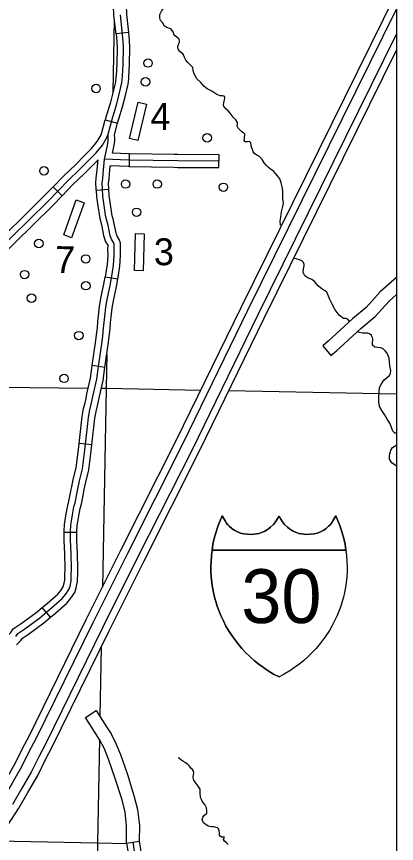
# Model space of a CAD drawing. Extents: x 1369979 to 1371646, y 379997 to 381064.
# Drawn here: x 1371088 to 1371140.4, y 380415 to 380529.1 of the extents above; entities that cross this region are included whole.
import ezdxf

# ---------------------------------------------------------------- set-up
doc = ezdxf.new("R2010")
doc.units = 0
doc.layers.add('R_Border Notes', color=7, linetype='Continuous')
doc.layers.add('R_No Plot', color=7, linetype='Continuous')

msp = doc.modelspace()

# ---------------------------------------------------------------- linework, layer by layer
at = {"layer": 'R_Border Notes'}
for p, q in [((1371103.48, 380526.85), (1371101.74, 380526.66)), ((1371140.38, 380526.67), (1371121.22, 380487.83)), ((1371122.11, 380487.39), (1371140.38, 380524.42)), ((1371101.73, 380520.69), (1371101.73, 380520.69)), ((1371100.26, 380514.82), (1371101.96, 380514.35)), ((1371103.56, 380510.15), (1371103.53, 380508.39)), ((1371109.75, 380510.04), (1371109.75, 380510.04)), ((1371115.92, 380508.25), (1371115.93, 380510)), ((1371094.33, 380504.36), (1371093.07, 380505.59)), ((1371093.07, 380505.59), (1371093.07, 380505.59)), ((1371100.74, 380505.22), (1371098.99, 380505.08)), ((1371098.99, 380505.08), (1371098.99, 380505.08)), ((1371100.24, 380493.19), (1371101.97, 380492.88)), ((1371121.22, 380487.83), (1371112.21, 380469.29)), ((1371113.26, 380469.17), (1371122.11, 380487.39)), ((1371130.22, 380483.65), (1371131.34, 380482.3)), ((1371100.21, 380480.67), (1371098.47, 380480.92)), ((1371098.42, 380470.01), (1371096.67, 380470.2)), ((1371112.21, 380469.29), (1371104.66, 380454.35)), ((1371105.55, 380453.9), (1371113.26, 380469.17)), ((1371096.34, 380457.93), (1371094.58, 380457.93)), ((1371133.43, 380455.45), (1371133.41, 380455.45)), ((1371104.66, 380454.35), (1371099.88, 380444.78)), ((1371100.77, 380444.33), (1371105.55, 380453.9)), ((1371092.71, 380446.24), (1371091.56, 380447.57)), ((1371099.88, 380444.78), (1371092.01, 380428.71)), ((1371092.91, 380428.27), (1371100.77, 380444.33)), ((1371103.19, 380415.08), (1371104.92, 380415.35))]:
    msp.add_line(p, q, dxfattribs=at)
for points in [[(1371109.63, 380526.97), (1371109.3, 380527.37), (1371108.98, 380527.48), (1371108.63, 380527.58), (1371108.39, 380527.8), (1371108.17, 380528.18), (1371107.86, 380528.53), (1371107.77, 380528.87), (1371107.77, 380529.35), (1371107.99, 380529.83), (1371108.41, 380530.38), (1371108.53, 380530.66), (1371108.87, 380531.26), (1371108.93, 380531.52), (1371109.11, 380531.92), (1371109.11, 380532.33), (1371108.9, 380532.81), (1371108.79, 380533.06), (1371108.6, 380533.56), (1371108.52, 380533.99), (1371108.53, 380534.45), (1371108.69, 380535.02), (1371108.88, 380535.57)], [(1371101.74, 380526.66), (1371101.45, 380529.23), (1371101.36, 380532.01), (1371101.4, 380532.79), (1371101.51, 380533.16)], [(1371103.48, 380526.85), (1371103.21, 380529.36), (1371103.12, 380531.99), (1371103.15, 380532.5), (1371103.2, 380532.67)], [(1371118.96, 380488.96), (1371140.38, 380532.36)], [(1371084.95, 380496.13), (1371085.29, 380496.48), (1371085.84, 380497.09), (1371086.77, 380498.08), (1371087.55, 380498.85), (1371089.73, 380501), (1371092.34, 380503.57), (1371095.18, 380506.51), (1371096.7, 380507.96), (1371099, 380510.28), (1371099.86, 380511.34), (1371100.49, 380512.37), (1371100.63, 380512.85), (1371101.29, 380515.23), (1371101.8, 380516.85), (1371102.12, 380518.18), (1371102.52, 380519.91), (1371102.63, 380520.84), (1371102.71, 380522.52), (1371102.77, 380524.78), (1371102.73, 380525.68), (1371102.33, 380529.3)], [(1371140.38, 380530.11), (1371119.86, 380488.51)], [(1371101.49, 380528.67), (1371101.28, 380518.65)], [(1371103.48, 380520.48), (1371103.51, 380520.77), (1371103.59, 380522.49), (1371103.65, 380524.79), (1371103.61, 380525.75), (1371103.48, 380526.85)], [(1371112.88, 380520.47), (1371112.47, 380521.26), (1371112.39, 380521.67), (1371112.33, 380522.02), (1371112.02, 380522.36), (1371111.61, 380522.74), (1371111.34, 380523.04), (1371111.15, 380523.44), (1371111.05, 380523.78), (1371110.96, 380523.92), (1371110.78, 380524.05), (1371110.57, 380524.22), (1371110.33, 380524.49), (1371110.24, 380524.73), (1371110.24, 380524.97), (1371110.35, 380525.2), (1371110.49, 380525.48), (1371110.48, 380525.69), (1371110.43, 380525.93), (1371110.13, 380526.2), (1371109.92, 380526.36), (1371109.74, 380526.52), (1371109.63, 380526.97)], [(1371101.74, 380526.66), (1371101.85, 380525.62), (1371101.89, 380524.77), (1371101.83, 380522.55), (1371101.76, 380520.92), (1371101.73, 380520.69)], [(1371101.73, 380520.69), (1371101.65, 380520.06), (1371101.27, 380518.38), (1371100.95, 380517.08), (1371100.44, 380515.48), (1371100.26, 380514.82)], [(1371101.96, 380514.35), (1371102.13, 380514.98), (1371102.65, 380516.61), (1371102.98, 380517.98), (1371103.39, 380519.76), (1371103.48, 380520.48)], [(1371118.44, 380513.93), (1371118.5, 380514.28), (1371118.46, 380514.47), (1371118.26, 380514.81), (1371117.88, 380515.19), (1371117.45, 380515.75), (1371117.17, 380516.05), (1371116.86, 380516.35), (1371116.59, 380516.69), (1371116.56, 380516.91), (1371116.58, 380517.18), (1371116.7, 380517.6), (1371116.74, 380517.77), (1371116.74, 380517.95), (1371116.64, 380518.07), (1371116.43, 380518.12), (1371116.11, 380518.12), (1371115.65, 380518.33), (1371114.92, 380518.78), (1371114.3, 380519.08), (1371113.85, 380519.46), (1371113.41, 380519.96), (1371112.88, 380520.47)], [(1371097.45, 380509.96), (1371098.35, 380510.86), (1371099.14, 380511.85), (1371099.68, 380512.73), (1371099.79, 380513.09), (1371100.26, 380514.82)], [(1371101.52, 380512.76), (1371101.96, 380514.35)], [(1371124.48, 380506.13), (1371124.32, 380506.67), (1371124.03, 380507.05), (1371123.76, 380507.36), (1371123.43, 380507.72), (1371123.01, 380508.03), (1371122.71, 380508.3), (1371122.49, 380508.52), (1371122.14, 380508.9), (1371121.88, 380509.33), (1371121.53, 380509.75), (1371121.13, 380509.96), (1371120.83, 380510.18), (1371120.65, 380510.4), (1371120.54, 380510.74), (1371120.42, 380511.07), (1371120.35, 380511.37), (1371120.3, 380511.63), (1371120.19, 380511.76), (1371120.08, 380511.82), (1371119.84, 380511.77), (1371119.54, 380511.77), (1371119.41, 380511.96), (1371119.46, 380512.2), (1371119.43, 380512.41), (1371119.49, 380512.67), (1371119.48, 380512.84), (1371119.3, 380513.02), (1371119.08, 380513.18), (1371118.84, 380513.38), (1371118.55, 380513.65), (1371118.44, 380513.93)], [(1371101.47, 380496.09), (1371101.46, 380496.98), (1371101.49, 380497.67), (1371101.38, 380497.92), (1371101.1, 380498.38), (1371100.94, 380498.83), (1371100.65, 380500.3), (1371100.47, 380500.94), (1371100.35, 380501.4), (1371100.06, 380503.34), (1371099.94, 380504.29), (1371099.86, 380505.3), (1371099.83, 380506.08), (1371099.9, 380506.75), (1371099.95, 380507.4), (1371100.16, 380509.41), (1371100.58, 380511.28), (1371100.67, 380511.95), (1371100.67, 380512.26), (1371100.63, 380512.85)], [(1371101.44, 380511.12), (1371101.55, 380511.89), (1371101.55, 380512.29), (1371101.52, 380512.76)], [(1371101.25, 380510.24), (1371101.44, 380511.09)], [(1371093.07, 380505.59), (1371094.57, 380507.14), (1371096.09, 380508.59), (1371097.45, 380509.96)], [(1371103.56, 380510.15), (1371103.47, 380510.15), (1371101.25, 380510.24)], [(1371109.75, 380510.04), (1371103.56, 380510.15)], [(1371115.93, 380510), (1371110.27, 380510.03), (1371109.75, 380510.04)], [(1371094.33, 380504.36), (1371095.8, 380505.89), (1371097.32, 380507.33), (1371099.27, 380509.3)], [(1371098.99, 380505.08), (1371098.98, 380505.25), (1371098.95, 380506.11), (1371099.02, 380506.83), (1371099.08, 380507.49), (1371099.27, 380509.3)], [(1371115.92, 380509.12), (1371110.26, 380509.15), (1371103.44, 380509.27), (1371100.16, 380509.41)], [(1371100.74, 380505.22), (1371100.74, 380505.35), (1371100.71, 380506.06), (1371100.77, 380506.67), (1371100.83, 380507.32), (1371100.95, 380508.5)], [(1371103.53, 380508.39), (1371103.42, 380508.39), (1371100.95, 380508.5)], [(1371103.53, 380508.39), (1371109.72, 380508.28)], [(1371109.72, 380508.28), (1371110.25, 380508.27), (1371115.92, 380508.25)], [(1371093.07, 380505.59), (1371091.71, 380504.19), (1371089.12, 380501.63), (1371088.71, 380501.23)], [(1371098.99, 380505.08), (1371099.06, 380504.2), (1371099.19, 380503.22), (1371099.49, 380501.23), (1371099.62, 380500.71), (1371099.79, 380500.1), (1371100.03, 380498.89)], [(1371101.76, 380499.23), (1371101.5, 380500.5), (1371101.32, 380501.16), (1371101.21, 380501.58), (1371100.93, 380503.46), (1371100.81, 380504.38), (1371100.74, 380505.22)], [(1371124.41, 380500.29), (1371124.37, 380500.85), (1371124.46, 380501.4), (1371124.53, 380502.15), (1371124.72, 380502.85), (1371124.8, 380503.32), (1371124.73, 380503.94), (1371124.73, 380504.88), (1371124.67, 380505.39)], [(1371124.67, 380505.39), (1371124.48, 380506.13)], [(1371089.94, 380499.97), (1371090.35, 380500.38), (1371092.96, 380502.95), (1371094.33, 380504.36)], [(1371088.71, 380501.23), (1371086.93, 380499.48), (1371086.14, 380498.7), (1371085.19, 380497.69), (1371084.64, 380497.08), (1371084.36, 380496.77)], [(1371085.64, 380495.58), (1371085.93, 380495.89), (1371086.48, 380496.5), (1371087.4, 380497.47), (1371088.17, 380498.23), (1371089.94, 380499.97)], [(1371124.46, 380499.74), (1371124.46, 380499.75)], [(1371100.03, 380498.89), (1371100.09, 380498.6), (1371100.3, 380497.99), (1371100.6, 380497.52), (1371100.6, 380497.51), (1371100.58, 380496.99), (1371100.59, 380496.11), (1371100.51, 380494.86), (1371100.33, 380493.7), (1371100.24, 380493.19)], [(1371101.97, 380492.88), (1371102.06, 380493.41), (1371102.25, 380494.66), (1371102.35, 380496.06), (1371102.34, 380496.97), (1371102.37, 380497.83), (1371102.16, 380498.32), (1371101.9, 380498.76), (1371101.79, 380499.06), (1371101.76, 380499.23)], [(1371100.91, 380491.99), (1371101.19, 380493.55), (1371101.38, 380494.76), (1371101.47, 380496.09)], [(1371133.07, 380487.44), (1371132.5, 380487.86), (1371131.94, 380488.64), (1371131.51, 380489.41), (1371131.18, 380490.03), (1371130.92, 380490.73), (1371130.78, 380491.04), (1371130.54, 380491.24), (1371130.16, 380491.47), (1371129.62, 380491.9), (1371129.33, 380492.26), (1371129.08, 380492.54), (1371128.74, 380492.82), (1371128.15, 380493.03), (1371127.77, 380493.3), (1371127.52, 380493.78), (1371127.56, 380494.27), (1371127.67, 380494.7), (1371127.66, 380494.88), (1371127.58, 380495.13), (1371127.34, 380495.37), (1371127.01, 380495.53), (1371126.7, 380495.6), (1371126.23, 380495.74)], [(1371099.23, 380487.01), (1371099.3, 380487.8), (1371099.48, 380489.11), (1371099.65, 380490.18), (1371099.82, 380491.09), (1371100.05, 380492.16), (1371100.24, 380493.19)], [(1371100.98, 380486.85), (1371101.05, 380487.6), (1371101.22, 380488.86), (1371101.38, 380489.88), (1371101.55, 380490.74), (1371101.78, 380491.82), (1371101.97, 380492.88)], [(1371140.38, 380493.1), (1371138.14, 380491.08), (1371136.23, 380488.95), (1371134.32, 380487.38), (1371130.97, 380484.28), (1371130.22, 380483.65)], [(1371099.34, 380480.79), (1371099.84, 380484.26), (1371099.94, 380485.05), (1371100.03, 380486.07), (1371100.18, 380487.7), (1371100.35, 380488.99), (1371100.51, 380490.03), (1371100.69, 380490.91), (1371100.91, 380491.99)], [(1371131.34, 380482.3), (1371132.13, 380482.96), (1371135.47, 380486.06), (1371137.45, 380487.68), (1371139.39, 380489.83), (1371140.38, 380490.73)], [(1371110.03, 380470.58), (1371118.96, 380488.96)], [(1371119.86, 380488.51), (1371110.94, 380470.17)], [(1371098.47, 380480.92), (1371098.97, 380484.37), (1371099.06, 380485.15), (1371099.16, 380486.15), (1371099.23, 380487.01)], [(1371100.21, 380480.67), (1371100.72, 380484.14), (1371100.81, 380484.96), (1371100.91, 380485.99), (1371100.98, 380486.85)], [(1371133.91, 380487.01), (1371133.84, 380487.14), (1371133.71, 380487.28), (1371133.47, 380487.41), (1371133.07, 380487.44)], [(1371139.48, 380480.96), (1371139.36, 380481.93), (1371139.11, 380482.66), (1371138.84, 380482.98), (1371138.57, 380483.23), (1371138.23, 380483.39), (1371137.79, 380483.43), (1371137.39, 380483.46), (1371137.07, 380483.73), (1371137.07, 380484.02), (1371137.12, 380484.57), (1371137.07, 380484.78), (1371136.93, 380485.07), (1371136.67, 380485.29), (1371136.45, 380485.39), (1371136.02, 380485.42), (1371135.7, 380485.42), (1371135.3, 380485.47), (1371135, 380485.62)], [(1371100.48, 380482.48), (1371100.38, 380477.81)], [(1371095.46, 380456.88), (1371095.46, 380458.03), (1371095.53, 380458.94), (1371095.59, 380459.49), (1371095.74, 380460.35), (1371095.94, 380461.44), (1371096.1, 380462), (1371096.42, 380463.69), (1371096.7, 380465.02), (1371097.1, 380466.69), (1371097.45, 380469.27), (1371097.93, 380473.79), (1371098.12, 380474.81), (1371098.33, 380475.59), (1371098.59, 380476.84), (1371099.1, 380479.05), (1371099.34, 380480.79)], [(1371097.6, 380476.39), (1371097.73, 380477.03), (1371098.23, 380479.21), (1371098.47, 380480.91)], [(1371099.32, 380476.04), (1371099.45, 380476.66), (1371099.96, 380478.89), (1371100.21, 380480.67)], [(1371139.65, 380472.51), (1371139.46, 380472.99), (1371139.09, 380473.52), (1371138.74, 380474.17), (1371138.39, 380474.74), (1371138.07, 380475.29), (1371137.96, 380475.91), (1371137.96, 380476.77), (1371137.98, 380477.18), (1371138.06, 380477.89), (1371138.34, 380478.41), (1371138.65, 380478.92), (1371139.01, 380479.24), (1371139.4, 380479.51), (1371139.57, 380479.85), (1371139.62, 380480.2), (1371139.48, 380480.96)], [(1371077.75, 380478.04), (1371097.91, 380477.83)], [(1371099.71, 380477.81), (1371100.38, 380477.81)], [(1371100.38, 380477.81), (1371099.86, 380450.37)], [(1371100.38, 380477.81), (1371113.42, 380477.55)], [(1371117.29, 380477.48), (1371140.38, 380477.03)], [(1371096.67, 380470.2), (1371097.06, 380473.92), (1371097.26, 380475.01), (1371097.48, 380475.79), (1371097.6, 380476.39)], [(1371098.42, 380470.01), (1371098.8, 380473.67), (1371098.98, 380474.61), (1371099.19, 380475.38), (1371099.32, 380476.04)], [(1371140.38, 380471.6), (1371140.14, 380471.63), (1371139.89, 380471.88), (1371139.73, 380472.27), (1371139.65, 380472.51)], [(1371095.63, 380464.2), (1371095.85, 380465.22), (1371096.24, 380466.85), (1371096.58, 380469.37), (1371096.67, 380470.2)], [(1371097.35, 380463.84), (1371097.56, 380464.83), (1371097.97, 380466.53), (1371098.32, 380469.16), (1371098.42, 380470.01)], [(1371102.4, 380455.46), (1371110.03, 380470.58)], [(1371110.94, 380470.17), (1371103.3, 380455.02)], [(1371140.38, 380467.07), (1371140.37, 380467.07), (1371139.76, 380467.5), (1371139.44, 380468.04), (1371139.41, 380468.57), (1371139.6, 380469.27), (1371139.83, 380469.65), (1371140.29, 380469.91), (1371140.38, 380469.96)], [(1371094.58, 380457.93), (1371094.58, 380458.07), (1371094.65, 380459.03), (1371094.72, 380459.62), (1371094.88, 380460.5), (1371095.09, 380461.65), (1371095.25, 380462.21), (1371095.56, 380463.86), (1371095.63, 380464.2)], [(1371096.34, 380457.93), (1371096.34, 380458), (1371096.4, 380458.86), (1371096.46, 380459.36), (1371096.61, 380460.19), (1371096.8, 380461.24), (1371096.96, 380461.8), (1371097.29, 380463.51), (1371097.35, 380463.84)], [(1371114.97, 380455.45), (1371115.1, 380456.3), (1371115.27, 380457.1), (1371115.49, 380457.88), (1371115.8, 380458.89), (1371116.35, 380460.2), (1371116.76, 380459.5), (1371116.94, 380459.21), (1371117.13, 380458.98), (1371117.35, 380458.76), (1371117.69, 380458.48), (1371118.03, 380458.24), (1371118.4, 380458.03), (1371118.88, 380457.84), (1371119.36, 380457.73), (1371119.86, 380457.66), (1371120.4, 380457.64), (1371120.79, 380457.67), (1371121.1, 380457.71), (1371121.44, 380457.79), (1371121.92, 380457.96), (1371122.23, 380458.09), (1371122.49, 380458.23), (1371122.74, 380458.4), (1371123.04, 380458.63), (1371123.44, 380459.02), (1371123.71, 380459.36), (1371123.94, 380459.73), (1371124.2, 380460.17)], [(1371124.2, 380460.17), (1371123.94, 380459.73), (1371123.71, 380459.36), (1371123.44, 380459.02), (1371123.04, 380458.63), (1371122.74, 380458.4), (1371122.49, 380458.23), (1371122.23, 380458.09), (1371121.92, 380457.96), (1371121.44, 380457.79), (1371121.1, 380457.71), (1371120.79, 380457.67), (1371120.4, 380457.64), (1371119.86, 380457.66), (1371119.36, 380457.73), (1371118.88, 380457.84), (1371118.4, 380458.03), (1371118.03, 380458.24), (1371117.69, 380458.48), (1371117.35, 380458.76), (1371117.13, 380458.98), (1371116.94, 380459.21), (1371116.76, 380459.5), (1371116.35, 380460.2), (1371115.8, 380458.89), (1371115.49, 380457.88), (1371115.27, 380457.1), (1371115.1, 380456.3), (1371114.97, 380455.45)], [(1371124.2, 380460.17), (1371124.45, 380459.73), (1371124.68, 380459.36), (1371124.96, 380459.02), (1371125.35, 380458.63), (1371125.65, 380458.4), (1371125.9, 380458.23), (1371126.16, 380458.09), (1371126.47, 380457.96), (1371126.95, 380457.79), (1371127.29, 380457.71), (1371127.61, 380457.67), (1371127.99, 380457.64), (1371128.53, 380457.66), (1371129.04, 380457.73), (1371129.51, 380457.84), (1371129.99, 380458.03), (1371130.36, 380458.24), (1371130.7, 380458.48), (1371131.04, 380458.76), (1371131.26, 380458.98), (1371131.45, 380459.21), (1371131.63, 380459.5), (1371132.05, 380460.2), (1371132.59, 380458.89), (1371132.91, 380457.88), (1371133.13, 380457.1), (1371133.3, 380456.3), (1371133.43, 380455.45)], [(1371133.43, 380455.45), (1371133.3, 380456.3), (1371133.13, 380457.1), (1371132.91, 380457.88), (1371132.59, 380458.89), (1371132.05, 380460.2), (1371131.63, 380459.5), (1371131.45, 380459.21), (1371131.26, 380458.98), (1371131.04, 380458.76), (1371130.7, 380458.48), (1371130.36, 380458.24), (1371129.99, 380458.03), (1371129.51, 380457.84), (1371129.04, 380457.73), (1371128.53, 380457.66), (1371127.99, 380457.64), (1371127.61, 380457.67), (1371127.29, 380457.71), (1371126.95, 380457.79), (1371126.47, 380457.96), (1371126.16, 380458.09), (1371125.9, 380458.23), (1371125.65, 380458.4), (1371125.35, 380458.63), (1371124.96, 380459.02), (1371124.68, 380459.36), (1371124.45, 380459.73), (1371124.2, 380460.17)], [(1371094.68, 380451.78), (1371094.69, 380451.95), (1371094.72, 380452.98), (1371094.66, 380454.91), (1371094.58, 380456.87), (1371094.58, 380457.93)], [(1371096.44, 380451.71), (1371096.45, 380451.89), (1371096.47, 380452.98), (1371096.42, 380454.97), (1371096.34, 380456.9), (1371096.34, 380457.93)], [(1371087.91, 380443.56), (1371088.19, 380443.98), (1371089.16, 380444.62), (1371091.23, 380446.12), (1371092.84, 380447.52), (1371094.33, 380448.8), (1371094.82, 380449.39), (1371095.25, 380450.03), (1371095.41, 380450.51), (1371095.54, 380451.25), (1371095.57, 380451.92), (1371095.59, 380452.98), (1371095.54, 380454.94), (1371095.46, 380456.88)], [(1371097.63, 380445.91), (1371102.4, 380455.46)], [(1371103.3, 380455.02), (1371098.52, 380445.46)], [(1371114.98, 380455.45), (1371114.89, 380454.69), (1371114.83, 380453.9), (1371114.81, 380453.17), (1371114.82, 380452.5), (1371114.86, 380451.73), (1371114.93, 380451.07), (1371115, 380450.58), (1371115.17, 380449.64), (1371115.32, 380448.98), (1371115.49, 380448.38), (1371115.68, 380447.77), (1371115.9, 380447.15), (1371116.18, 380446.48), (1371116.53, 380445.71), (1371116.89, 380445.01), (1371117.25, 380444.39), (1371117.82, 380443.52), (1371118.51, 380442.58), (1371119.09, 380441.9), (1371119.6, 380441.35), (1371120.16, 380440.8), (1371120.83, 380440.2), (1371121.45, 380439.7), (1371122.05, 380439.27), (1371122.7, 380438.83), (1371123.46, 380438.38), (1371124.2, 380437.99)], [(1371124.2, 380437.99), (1371123.46, 380438.38), (1371122.7, 380438.83), (1371122.05, 380439.27), (1371121.45, 380439.7), (1371120.83, 380440.2), (1371120.16, 380440.8), (1371119.6, 380441.35), (1371119.09, 380441.9), (1371118.51, 380442.58), (1371117.82, 380443.52), (1371117.25, 380444.39), (1371116.89, 380445.01), (1371116.53, 380445.71), (1371116.18, 380446.48), (1371115.9, 380447.15), (1371115.68, 380447.77), (1371115.49, 380448.38), (1371115.32, 380448.98), (1371115.17, 380449.64), (1371115, 380450.58), (1371114.93, 380451.07), (1371114.86, 380451.73), (1371114.82, 380452.5), (1371114.81, 380453.17), (1371114.83, 380453.9), (1371114.89, 380454.69), (1371114.98, 380455.45)], [(1371133.43, 380455.45), (1371114.97, 380455.45)], [(1371114.97, 380455.45), (1371133.43, 380455.45)], [(1371114.97, 380455.45), (1371133.43, 380455.45)], [(1371133.41, 380455.45), (1371133.5, 380454.69), (1371133.56, 380453.9), (1371133.58, 380453.17), (1371133.57, 380452.5), (1371133.53, 380451.73), (1371133.46, 380451.07), (1371133.4, 380450.58), (1371133.22, 380449.64), (1371133.07, 380448.98), (1371132.9, 380448.38), (1371132.71, 380447.77), (1371132.49, 380447.15), (1371132.22, 380446.48), (1371131.86, 380445.71), (1371131.5, 380445.01), (1371131.14, 380444.39), (1371130.57, 380443.52), (1371129.88, 380442.58), (1371129.3, 380441.9), (1371128.79, 380441.35), (1371128.23, 380440.8), (1371127.56, 380440.2), (1371126.94, 380439.7), (1371126.35, 380439.27), (1371125.7, 380438.83), (1371124.93, 380438.38), (1371124.2, 380437.99)], [(1371133.41, 380455.45), (1371133.5, 380454.69), (1371133.56, 380453.9), (1371133.58, 380453.17), (1371133.57, 380452.5), (1371133.53, 380451.73), (1371133.46, 380451.07), (1371133.4, 380450.58), (1371133.22, 380449.64), (1371133.07, 380448.98), (1371132.9, 380448.38), (1371132.71, 380447.77), (1371132.49, 380447.15), (1371132.22, 380446.48), (1371131.86, 380445.71), (1371131.5, 380445.01), (1371131.14, 380444.39), (1371130.57, 380443.52), (1371129.88, 380442.58), (1371129.3, 380441.9), (1371128.79, 380441.35), (1371128.23, 380440.8), (1371127.56, 380440.2), (1371126.94, 380439.7), (1371126.35, 380439.27), (1371125.7, 380438.83), (1371124.93, 380438.38), (1371124.2, 380437.99)], [(1371091.56, 380447.57), (1371092.27, 380448.18), (1371093.7, 380449.42), (1371094.12, 380449.92), (1371094.45, 380450.42), (1371094.55, 380450.73), (1371094.67, 380451.34), (1371094.68, 380451.78)], [(1371092.71, 380446.24), (1371093.42, 380446.85), (1371094.95, 380448.18), (1371095.52, 380448.86), (1371096.04, 380449.64), (1371096.26, 380450.29), (1371096.42, 380451.15), (1371096.44, 380451.71)], [(1371086.72, 380443.6), (1371086.77, 380443.64), (1371087.23, 380444.12), (1371087.56, 380444.61), (1371088.65, 380445.34), (1371090.68, 380446.81), (1371091.56, 380447.57)], [(1371088.03, 380442.42), (1371088.05, 380442.44), (1371088.6, 380443.01), (1371088.83, 380443.34), (1371089.66, 380443.9), (1371091.77, 380445.43), (1371092.71, 380446.24)], [(1371089.75, 380429.82), (1371097.63, 380445.91)], [(1371098.52, 380445.46), (1371090.65, 380429.38)], [(1371099.7, 380442.15), (1371099.52, 380432.52)], [(1371098.96, 380430.15), (1371097.51, 380432.41), (1371098.99, 380433.36)], [(1371098.99, 380433.36), (1371100.44, 380431.1)], [(1371100.44, 380431.09), (1371101.05, 380430.12), (1371101.73, 380428.83), (1371102.37, 380427.3), (1371103.31, 380424.53), (1371104.21, 380421.66), (1371104.71, 380419.71), (1371104.96, 380417.48), (1371104.92, 380415.35)], [(1371085.29, 380421.63), (1371086.54, 380423.82), (1371087.84, 380426.05), (1371088.89, 380428.2), (1371089.75, 380429.82)], [(1371103.19, 380415.08), (1371103.2, 380417.39), (1371102.98, 380419.39), (1371102.52, 380421.18), (1371101.64, 380423.98), (1371100.72, 380426.67), (1371100.13, 380428.08), (1371099.52, 380429.25), (1371098.96, 380430.16)], [(1371090.65, 380429.38), (1371089.78, 380427.75), (1371088.71, 380425.58), (1371087.4, 380423.32), (1371086.15, 380421.14)], [(1371092.01, 380428.71), (1371091.14, 380427.06), (1371090.06, 380424.86), (1371088.72, 380422.56), (1371087.47, 380420.38)], [(1371099.46, 380429.37), (1371099.19, 380415.11)], [(1371088.34, 380419.89), (1371089.58, 380422.07), (1371090.94, 380424.39), (1371092.03, 380426.61), (1371092.91, 380428.27)], [(1371112.35, 380424.2), (1371112.44, 380424.77), (1371112.42, 380424.98), (1371112.28, 380425.23), (1371112.1, 380425.38), (1371111.85, 380425.68), (1371111.65, 380425.91), (1371111.47, 380426.06), (1371111.27, 380426.17), (1371110.94, 380426.36), (1371110.44, 380426.73), (1371110.38, 380426.91)], [(1371113.9, 380418.87), (1371114.24, 380419.2), (1371114.24, 380419.55), (1371114.19, 380419.94), (1371113.97, 380420.38), (1371113.65, 380420.76), (1371113.5, 380421.08), (1371113.4, 380421.35), (1371113.31, 380422), (1371113.33, 380422.49), (1371113.07, 380422.91), (1371112.65, 380423.49), (1371112.42, 380423.85), (1371112.35, 380424.2)], [(1371083.96, 380413.38), (1371085.62, 380415.77), (1371086.84, 380417.56), (1371088.34, 380419.89)], [(1371113.74, 380417.95), (1371113.63, 380418.35), (1371113.69, 380418.67), (1371113.9, 380418.87)], [(1371116.7, 380415.87), (1371116.31, 380415.9), (1371116.1, 380416.05), (1371115.99, 380416.19), (1371115.99, 380416.43), (1371115.95, 380416.75), (1371115.87, 380417.02), (1371115.72, 380417.16), (1371115.21, 380417.31), (1371114.89, 380417.33), (1371114.42, 380417.43), (1371113.98, 380417.71), (1371113.78, 380417.87), (1371113.74, 380417.95)], [(1371085.36, 380415.4), (1371099.19, 380415.11)], [(1371099.19, 380415.11), (1371099.22, 380402.14)], [(1371099.19, 380415.11), (1371103.19, 380415.04)], [(1371103.19, 380415.08), (1371103.44, 380413.47), (1371103.65, 380412.85), (1371104.15, 380411.93), (1371104.45, 380411.42), (1371104.48, 380411.06), (1371104.47, 380410.57), (1371104.11, 380409.9), (1371104.04, 380409.61)], [(1371104.06, 380415.21), (1371104.3, 380413.68)], [(1371104.92, 380415.35), (1371105.15, 380413.89), (1371105.27, 380413.55), (1371105.67, 380412.81), (1371106.17, 380411.98), (1371106.25, 380411.11), (1371106.21, 380410.1), (1371105.77, 380409.28), (1371105.75, 380409.21)], [(1371117.21, 380414.9), (1371116.95, 380415.1), (1371116.69, 380415.35), (1371116.55, 380415.55), (1371116.58, 380415.7), (1371116.7, 380415.87)]]:
    msp.add_lwpolyline(points, dxfattribs=at)
for points in [[(1371104.72, 380511.99), (1371103.59, 380512.27), (1371104.81, 380517.25), (1371105.95, 380516.97)], [(1371096.24, 380503.78), (1371097.35, 380503.39), (1371095.62, 380498.56), (1371094.52, 380498.95)], [(1371104.43, 380499.15), (1371105.61, 380499.12), (1371105.46, 380493.99), (1371104.29, 380494.02)]]:
    msp.add_lwpolyline(points, close=True, dxfattribs=at)
for centre in [(1371106.15, 380522.65), (1371105.8, 380520.06), (1371098.98, 380519.14), (1371114.29, 380512.35), (1371091.8, 380507.78), (1371103.06, 380505.97), (1371107.42, 380505.97), (1371116.53, 380505.52), (1371104.57, 380502.07), (1371091.1, 380497.77), (1371097.56, 380495.64), (1371089.14, 380493.47), (1371097.57, 380491.94), (1371090.09, 380490.23), (1371096.6, 380485.06), (1371094.57, 380479.16)]:
    msp.add_circle(centre, 0.586, dxfattribs=at)
at = {"layer": 'R_No Plot'}
msp.add_lwpolyline([(1370544.5, 380586.87), (1371140.38, 380586.87), (1371140.38, 380146.39), (1370544.5, 380146.39)], close=True, dxfattribs=at)

# ---------------------------------------------------------------- texts
at = {"layer": 'R_Border Notes'}
for s, height, p in [('4', 3.71, (1371106.47, 380513.43)), ('3', 3.71, (1371106.95, 380494.77)), ('30', 7.425, (1371119, 380445.42))]:
    msp.add_text(s, height=height, dxfattribs=at).set_placement(p)
msp.add_text('7', height=3.71, rotation=358.5666, dxfattribs=at).set_placement((1371093.28, 380493.71))

doc.saveas('drawing.dxf')
